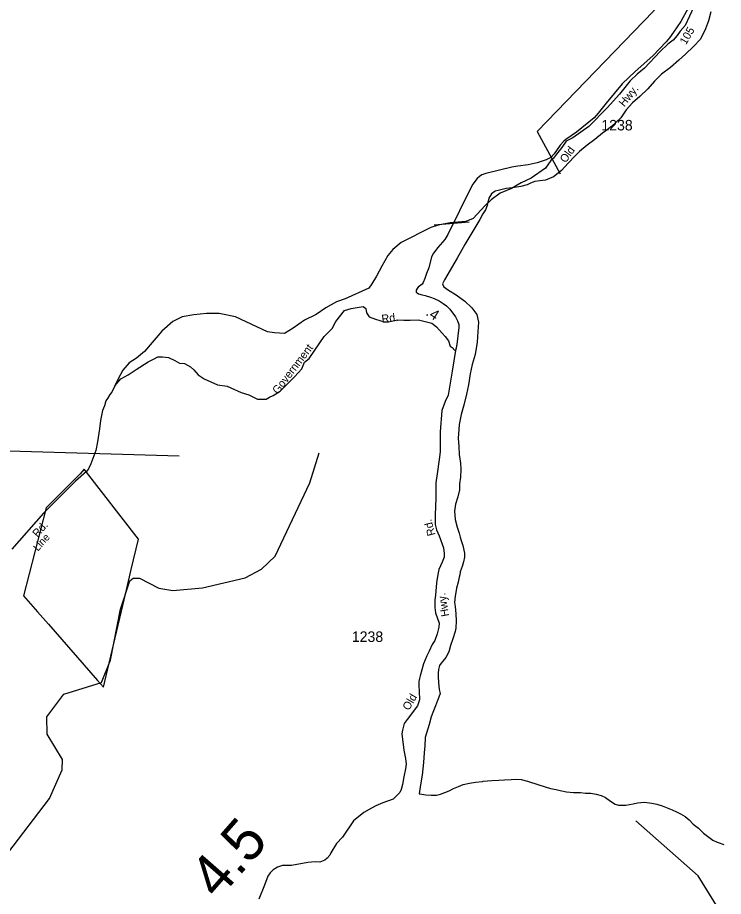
# Model space of a CAD drawing. Extents: x 1113032 to 1302912, y 664689 to 832535.
# Drawn here: x 1126972 to 1135345, y 765901 to 776333 of the extents above; entities that cross this region are included whole.
import ezdxf

# ---------------------------------------------------------------- set-up
doc = ezdxf.new("R2010")
doc.units = 0
for name, color, linetype in [('Exist Boundary Land Use Forest National US Forest Service', 7, 'Continuous'), ('Exist Boundary Political CountyLine', 7, 'Continuous'), ('Exist Boundary Political CountyLine Road Label', 7, 'Continuous'), ('Exist Hydrographic Creek Single Shore', 7, 'Continuous'), ('Exist Road Secondary Mileage Hundredths English Label', 7, 'Continuous'), ('Exist Road Secondary Type 41 Attributed', 7, 'Continuous'), ('Exist Road Secondary Type 51 Label', 7, 'Continuous'), ('Exist Road Secondary Type 51 Number Label', 7, 'Continuous'), ('Exist Road State Agency Type 20 National Forest', 7, 'Continuous'), ('Map Preparation Longitude Latitude Lines', 7, 'Continuous')]:
    doc.layers.add(name, color=color, linetype=linetype)

msp = doc.modelspace()

# ---------------------------------------------------------------- linework, layer by layer
at = {"layer": 'Exist Boundary Land Use Forest National US Forest Service'}
for points in [[(1135196, 776402), (1135169, 776295), (1135132, 776200), (1135074, 776076), (1134989, 775991), (1134894, 775900), (1134817, 775828), (1134717, 775741), (1134612, 775662), (1134529, 775577), (1134448, 775486), (1134353, 775395), (1134267, 775321), (1134192, 775236), (1134129, 775144), (1134017, 775039), (1133949, 774988), (1133911, 774960), (1133820, 774885), (1133730, 774818), (1133639, 774743), (1133581, 774689), (1133505, 774605), (1133426, 774518), (1133329, 774443), (1133236, 774402), (1133169, 774394), (1133107, 774388), (1133055, 774368), (1133016, 774347), (1132943, 774329), (1132844, 774310), (1132766, 774303), (1132752, 774301), (1132674, 774281), (1132637, 774271), (1132592, 774240), (1132562, 774191), (1132562, 774188), (1132555, 774155), (1132552, 774140), (1132544, 774104), (1132522, 774052), (1132492, 774005), (1132454, 773936), (1132278, 773638), (1132185, 773477), (1132036, 773221), (1132013, 773174), (1132028, 773136), (1132082, 773096), (1132175, 773041), (1132278, 772967), (1132362, 772887), (1132421, 772807), (1132438, 772716), (1132433, 772608), (1132425, 772480), (1132400, 772335), (1132366, 772216), (1132340, 772106), (1132320, 771973)], [(1132320, 771973), (1132297, 771862), (1132266, 771733), (1132233, 771622), (1132209, 771502), (1132205, 771442), (1132197, 771340), (1132208, 771240), (1132211, 771148), (1132226, 771045), (1132232, 770973), (1132227, 770879), (1132216, 770799), (1132214, 770727), (1132195, 770644), (1132166, 770557), (1132155, 770473), (1132164, 770377), (1132185, 770284), (1132209, 770213), (1132222, 770165), (1132230, 770136), (1132252, 770067), (1132273, 769975), (1132274, 769927), (1132262, 769871), (1132246, 769819), (1132222, 769754), (1132217, 769719), (1132212, 769692), (1132200, 769631), (1132180, 769559), (1132170, 769510), (1132163, 769464), (1132156, 769392), (1132161, 769342), (1132170, 769255), (1132175, 769171), (1132172, 769085), (1132161, 769047), (1132134, 768960), (1132107, 768879), (1132087, 768806), (1132053, 768737), (1132017, 768694), (1131997, 768670), (1131978, 768641), (1131966, 768595), (1131961, 768551), (1131961, 768509), (1131965, 768441), (1131972, 768357), (1131985, 768308), (1131956, 768233), (1131954, 768227), (1131930, 768164), (1131904, 768105), (1131878, 768032), (1131853, 767942), (1131823, 767839), (1131808, 767786), (1131803, 767690), (1131794, 767604), (1131786, 767490), (1131771, 767341), (1131753, 767225), (1131734, 767120), (1131738, 767119), (1131768, 767114), (1131814, 767109), (1131878, 767105), (1131942, 767103), (1131988, 767115), (1132039, 767136), (1132092, 767156), (1132142, 767182), (1132203, 767208), (1132258, 767229), (1132333, 767244), (1132405, 767256), (1132489, 767267), (1132496, 767268), (1132598, 767278), (1132680, 767281), (1132750, 767287), (1132828, 767288), (1132895, 767294), (1132947, 767291), (1133022, 767268), (1133157, 767224), (1133295, 767183), (1133359, 767171), (1133407, 767160), (1133482, 767143), (1133566, 767134), (1133648, 767134), (1133710, 767128), (1133774, 767126), (1133836, 767116), (1133893, 767098)], [(1127919, 768466), (1127990, 768384), (1128022, 768520), (1128255, 769506), (1128320, 769781), (1128405, 770141), (1127761, 770971), (1127716, 770917), (1127658, 770861), (1127536, 770741), (1127313, 770515), (1127042, 769471), (1127209, 769280), (1127337, 769133), (1127919, 768466)], [(1133893, 767098), (1133946, 767074), (1134007, 767032), (1134060, 766998), (1134100, 766983), (1134140, 766984), (1134186, 766986), (1134232, 766993), (1134274, 767001), (1134327, 767012), (1134366, 767016), (1134409, 767021), (1134495, 767010), (1134557, 766998), (1134620, 766978), (1134738, 766930), (1134790, 766905), (1134837, 766883), (1134892, 766849), (1134939, 766810), (1134987, 766758), (1135048, 766710), (1135108, 766654), (1135170, 766604), (1135219, 766569), (1135271, 766546), (1135282, 766541), (1135348, 766518)]]:
    msp.add_lwpolyline(points, dxfattribs=at)
at = {"layer": 'Exist Boundary Political CountyLine'}
msp.add_line((1132327, 773903), (1131915, 773870), dxfattribs=at)
for points in [[(1139131, 788616), (1138765, 788791), (1138115, 787600), (1137351, 786367), (1137158, 785763), (1137062, 785351), (1136354, 783223), (1136025, 782582), (1135511, 781649), (1135257, 780312), (1135119, 779246), (1135086, 777401), (1134515, 776410), (1133137, 774982), (1133408, 774478)], [(1134994, 776459), (1134890, 776238), (1134832, 776171), (1134796, 776119), (1134748, 776064), (1134687, 776016), (1134594, 775928), (1134409, 775734), (1134320, 775662), (1134238, 775581), (1134113, 775424), (1133964, 775261), (1133747, 775041), (1133559, 774904), (1133480, 774864), (1133428, 774790), (1133364, 774712), (1133328, 774663), (1133297, 774638), (1133233, 774545), (1133065, 774428), (1132947, 774372), (1132833, 774305), (1132695, 774249), (1132589, 774168), (1132517, 774101), (1132376, 773948)], [(1132376, 773948), (1132289, 773913), (1132103, 773898), (1131960, 773869), (1131875, 773839), (1131521, 773662), (1131425, 773580), (1131363, 773510), (1131293, 773382), (1131231, 773262), (1131176, 773171), (1131139, 773122), (1130859, 772993), (1130754, 772960), (1130630, 772889), (1130515, 772809), (1130375, 772743), (1130240, 772645), (1130139, 772584), (1130021, 772589), (1129937, 772604), (1129558, 772781), (1129365, 772821), (1129213, 772821), (1129062, 772805), (1128924, 772780), (1128814, 772725), (1128682, 772609), (1128479, 772368), (1128383, 772289), (1128295, 772234), (1128222, 772148), (1128161, 772038), (1128091, 771887), (1128066, 771858), (1128038, 771811), (1128019, 771785), (1128004, 771726), (1127980, 771667), (1127955, 771551), (1127943, 771450), (1127921, 771298), (1127900, 771193), (1127843, 771034), (1127812, 770975), (1127789, 770944), (1127659, 770830), (1127280, 770451), (1126903, 770025)]]:
    msp.add_lwpolyline(points, dxfattribs=at)
at = {"layer": 'Exist Hydrographic Creek Single Shore'}
for points in [[(1126855, 766414), (1127350, 767064), (1127501, 767402), (1127505, 767527), (1127322, 767826), (1127320, 768033), (1127520, 768301), (1127966, 768440), (1128074, 768704), (1128192, 769309), (1128302, 769648), (1128344, 769680), (1128419, 769678), (1128649, 769562), (1128815, 769533), (1129167, 769565), (1129670, 769683), (1129865, 769784), (1130028, 769938), (1130437, 770810), (1130548, 771165)], [(1136308, 762631), (1136150, 763228), (1136096, 763371), (1136121, 763646), (1136185, 763818), (1136187, 764186), (1136151, 764377), (1135796, 764765), (1135692, 764934), (1135538, 765088), (1135428, 765301), (1135283, 765763), (1135044, 766145), (1134305, 766800)]]:
    msp.add_lwpolyline(points, dxfattribs=at)
at = {"layer": 'Exist Road Secondary Type 41 Attributed'}
for points in [[(1135105, 776774), (1134838, 776286), (1134753, 776158), (1134707, 776091), (1134664, 776043), (1134508, 775879), (1134300, 775691), (1134144, 775546), (1133956, 775317), (1133861, 775199), (1133811, 775141), (1133602, 774973), (1133476, 774886), (1133450, 774864), (1133408, 774818), (1133339, 774717), (1133297, 774672), (1133275, 774659), (1133244, 774643), (1133134, 774607), (1133028, 774586), (1132905, 774569), (1132837, 774556), (1132526, 774483), (1132481, 774465), (1132450, 774447), (1132424, 774422), (1132373, 774355), (1132354, 774318), (1132074, 773759), (1132041, 773699), (1131956, 773604), (1131904, 773538), (1131882, 773493), (1131851, 773362), (1131823, 773295), (1131805, 773234), (1131785, 773188), (1131770, 773167), (1131723, 773134), (1131708, 773114), (1131707, 773111), (1131701, 773096), (1131700, 773085), (1131702, 773075), (1131713, 773066), (1131726, 773054), (1131770, 773041), (1131807, 773033), (1131871, 773016), (1131914, 772998), (1131974, 772970), (1132022, 772939), (1132061, 772910), (1132098, 772872), (1132166, 772782), (1132191, 772735), (1132208, 772689), (1132208, 772650), (1132200, 772592), (1132185, 772484), (1132175, 772408), (1132167, 772381)], [(1132167, 772381), (1132128, 772134), (1132080, 771852), (1132044, 771777), (1132003, 771670), (1131983, 771416), (1131985, 771177), (1131975, 771087), (1131949, 770919), (1131933, 770812), (1131932, 770633), (1131930, 770525), (1131925, 770435), (1131925, 770315), (1131941, 770253), (1131973, 770180), (1132025, 770039), (1132033, 769970), (1132031, 769928), (1132008, 769867), (1131968, 769781), (1131958, 769723), (1131941, 769624), (1131929, 769476), (1131920, 769422), (1131921, 769330), (1131929, 769266), (1131974, 769145), (1131971, 769097), (1131951, 769017), (1131920, 768939), (1131892, 768890), (1131855, 768813), (1131825, 768757), (1131789, 768663), (1131746, 768521), (1131739, 768488), (1131730, 768451), (1131730, 768399), (1131737, 768339), (1131741, 768235), (1131728, 768199), (1131716, 768162), (1131592, 768000), (1131558, 767952), (1131537, 767873), (1131532, 767831), (1131555, 767638), (1131574, 767538), (1131582, 767472), (1131573, 767414), (1131554, 767320), (1131540, 767229), (1131524, 767171), (1131506, 767134), (1131427, 767054), (1131304, 767012), (1131221, 766975), (1131171, 766949), (1131080, 766898), (1130956, 766798), (1130828, 766605), (1130757, 766529), (1130688, 766418), (1130675, 766390), (1130645, 766355), (1130617, 766331), (1130558, 766309), (1130504, 766311), (1130417, 766305), (1130222, 766269), (1130114, 766269), (1130056, 766250), (1130002, 766218), (1129967, 766182), (1129941, 766142), (1129900, 766035), (1129833, 765870)]]:
    msp.add_lwpolyline(points, dxfattribs=at)
at = {"layer": 'Exist Road State Agency Type 20 National Forest'}
for points in [[(1130559, 772474), (1130610, 772548), (1130705, 772644), (1130746, 772724), (1130850, 772856), (1130929, 772878), (1131071, 772904), (1131105, 772878), (1131110, 772828), (1131142, 772780), (1131216, 772754), (1131320, 772723), (1131372, 772721), (1131477, 772747), (1131555, 772741), (1131629, 772743), (1131729, 772745), (1131887, 772704), (1131941, 772663), (1132009, 772586), (1132046, 772547), (1132083, 772497), (1132105, 772433), (1132128, 772418), (1132159, 772381)], [(1128126, 771963), (1128197, 772043), (1128284, 772094), (1128380, 772157), (1128521, 772245), (1128585, 772278), (1128635, 772304), (1128693, 772307), (1128762, 772298), (1128836, 772263), (1128894, 772232), (1128951, 772227), (1129024, 772189), (1129061, 772153), (1129116, 772093), (1129185, 772044), (1129343, 771973), (1129458, 771957), (1129503, 771937), (1129623, 771881), (1129714, 771854), (1129818, 771805), (1129919, 771804), (1129960, 771826), (1130003, 771845), (1130088, 771899), (1130188, 772001), (1130258, 772067), (1130345, 772162), (1130377, 772242), (1130430, 772286), (1130559, 772474)]]:
    msp.add_lwpolyline(points, dxfattribs=at)
at = {"layer": 'Map Preparation Longitude Latitude Lines'}
msp.add_line((1114014, 771573), (1128888, 771129), dxfattribs=at)

# ---------------------------------------------------------------- texts
at = {"layer": 'Exist Boundary Political CountyLine Road Label'}
msp.add_text('Line', height=88.6, rotation=48.448, dxfattribs=at).set_placement((1127213, 769992))
at = {"layer": 'Exist Road Secondary Mileage Hundredths English Label'}
for s, height, rotation, p in [('.4', 125, 326.9952, (1131806, 772807)), ('4.5', 500, 48.8484, (1129350, 765849))]:
    msp.add_text(s, height=height, rotation=rotation, dxfattribs=at).set_placement(p)
at = {"layer": 'Exist Road Secondary Type 51 Label'}
for s, rotation, p in [('105', 59.8858, (1134901, 776003)), ('Hwy.', 50.8406, (1134168, 775267)), ('Old', 53.8254, (1133472, 774600)), ('Rd.', 6.5012, (1131295, 772709)), ('Government', 52.6364, (1130060, 771856)), ('Rd.', 104.6884, (1131930, 770194)), ('Rd.', 48.448, (1127209, 770157)), ('Hwy.', 99.9037, (1132093, 769231)), ('Old', 59.2994, (1131613, 768101))]:
    msp.add_text(s, height=95, rotation=rotation, dxfattribs=at).set_placement(p)
at = {"layer": 'Exist Road Secondary Type 51 Number Label'}
for p in [(1133897, 774993), (1130937, 768922)]:
    msp.add_text('1238', height=125, dxfattribs=at).set_placement(p)

doc.saveas('drawing.dxf')
